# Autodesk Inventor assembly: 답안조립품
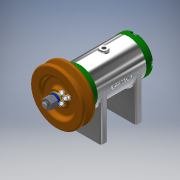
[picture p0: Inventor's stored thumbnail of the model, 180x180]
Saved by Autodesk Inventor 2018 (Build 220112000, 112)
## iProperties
Created: 2020-07
Part Number: 답안조립품
Material: 일반
Document SubType Name: Assembly
Designer: home
Author: home
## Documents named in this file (15)
- C:\Users\home\Desktop\700706V1036\답안조립품.iam
- C:\Users\home\Desktop\700706V1036\본체.ipt
- C:\Users\home\Desktop\700706V1036\베어링 6002.ipt
- C:\Users\home\Desktop\700706V1036\앞커버.ipt
- C:\Users\home\Desktop\700706V1036\뒤커버.ipt
- C:\Users\home\Desktop\700706V1036\오일 실 15 25 7.ipt
- C:\Users\home\Desktop\700706V1036\축.ipt
- C:\Users\home\Desktop\700706V1036\키 3x3x12.ipt
- C:\Users\home\Desktop\700706V1036\V벨트풀리.ipt
- C:\Users\home\Desktop\700706V1036\와셔 8x17.ipt
- C:\Users\home\Desktop\700706V1036\스프링와셔 8.ipt
- C:\Users\home\Desktop\700706V1036\너트 M8.ipt
- C:\Users\home\Desktop\700706V1036\볼트 M4x12.ipt
- C:\Users\home\Desktop\700706V1036\와셔 6x11.5.ipt
- C:\Users\home\Desktop\700706V1036\볼트 M6x8.ipt
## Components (1 placed, 1 different names)
1. V벨트풀리:1
